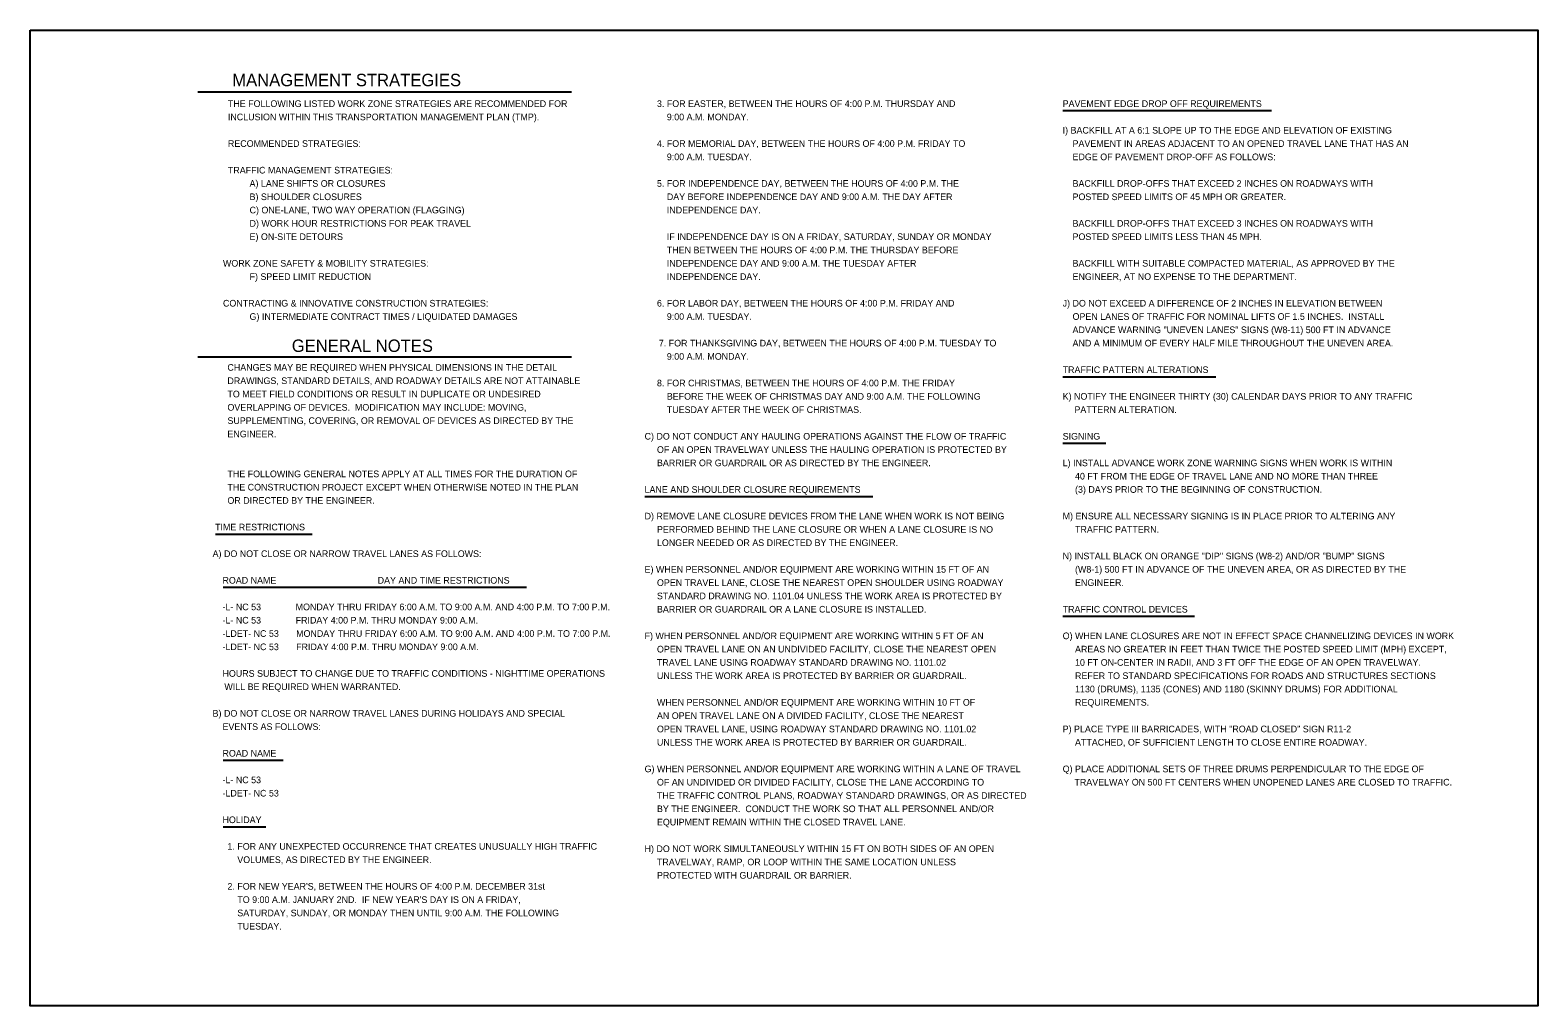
# Model space of a CAD drawing. Extents: x 0 to 3600, y 0 to 1100.
# Drawn here: x 0 to 1700, y 0 to 1100 of the extents above; entities that cross this region are included whole.
import ezdxf

# ---------------------------------------------------------------- set-up
doc = ezdxf.new("R2010")
doc.units = 0
for name, color, linetype in [('DEV BORDER CELL', 7, 'Continuous'), ('Prop Grid Mask', 7, 'Continuous'), ('Sheet Plan CELL', 7, 'Continuous'), ('Sheet_Plan', 7, 'Continuous'), ('Sheet_RDY_XS_Number', 7, 'Continuous')]:
    doc.layers.add(name, color=color, linetype=linetype)

msp = doc.modelspace()

# ---------------------------------------------------------------- linework, layer by layer
at = {"layer": 'DEV BORDER CELL'}
for p, q in [((189, 1030.3), (610.4, 1030.3)), ((189, 731.8), (610.4, 731.8))]:
    msp.add_line(p, q, dxfattribs=at)
at = {"layer": 'Sheet Plan CELL'}
msp.add_lwpolyline([(0, 1100), (1700, 1100), (1700, 0), (0, 0)], close=True, dxfattribs=at)
at = {"layer": 'Sheet_RDY_XS_Number'}
for p, q in [((1164.4, 1009.3), (1399.7, 1009.3)), ((1164.4, 709.3), (1337, 709.3)), ((1164.4, 634.3), (1212.7, 634.3)), ((693, 574.3), (950.3, 574.3)), ((208.8, 531.9), (317.8, 531.9)), ((217.6, 471.9), (559.7, 471.9)), ((1164.4, 439.3), (1313, 439.3)), ((217.6, 276.9), (285.2, 276.9)), ((217.6, 201.9), (265.8, 201.9))]:
    msp.add_line(p, q, dxfattribs=at)

# ---------------------------------------------------------------- texts
at = {"layer": 'Prop Grid Mask'}
for s, p in [('  THE FOLLOWING LISTED WORK ZONE STRATEGIES ARE RECOMMENDED FOR  ', (217.4, 1013.4)), ('            3. FOR EASTER, BETWEEN THE HOURS OF 4:00 P.M. THURSDAY AND', (673.3, 1013.4)), ('       PAVEMENT EDGE DROP OFF REQUIREMENTS', (1144.7, 1013.4)), ('  INCLUSION WITHIN THIS TRANSPORTATION MANAGEMENT PLAN (TMP).  ', (217.4, 998.4)), ('                9:00 A.M. MONDAY.', (673.3, 998.4)), ('       I) BACKFILL AT A 6:1 SLOPE UP TO THE EDGE AND ELEVATION OF EXISTING', (1144.7, 983.4)), ('  RECOMMENDED STRATEGIES:', (217.4, 968.4)), ('            4. FOR MEMORIAL DAY, BETWEEN THE HOURS OF 4:00 P.M. FRIDAY TO', (673.3, 968.4)), ('           PAVEMENT IN AREAS ADJACENT TO AN OPENED TRAVEL LANE THAT HAS AN ', (1144.7, 968.4)), ('                9:00 A.M. TUESDAY.', (673.3, 953.4)), ('           EDGE OF PAVEMENT DROP-OFF AS FOLLOWS:', (1144.7, 953.4)), ('  TRAFFIC MANAGEMENT STRATEGIES:', (217.4, 938.4)), ('A) LANE SHIFTS OR CLOSURES', (247.4, 923.4)), ('            5. FOR INDEPENDENCE DAY, BETWEEN THE HOURS OF 4:00 P.M. THE', (673.3, 923.4)), ('           BACKFILL DROP-OFFS THAT EXCEED 2 INCHES ON ROADWAYS WITH', (1144.7, 923.4)), ('C) ONE-LANE, TWO WAY OPERATION (FLAGGING)', (247.4, 893.4)), ('B) SHOULDER CLOSURES', (247.4, 908.4)), ('                DAY BEFORE INDEPENDENCE DAY AND 9:00 A.M. THE DAY AFTER', (673.3, 908.4)), ('                INDEPENDENCE DAY.', (673.3, 893.4)), ('           POSTED SPEED LIMITS OF 45 MPH OR GREATER.', (1144.7, 908.4)), ('D) WORK HOUR RESTRICTIONS FOR PEAK TRAVEL', (247.4, 878.4)), ('           BACKFILL DROP-OFFS THAT EXCEED 3 INCHES ON ROADWAYS WITH', (1144.7, 878.4)), ('E) ON-SITE DETOURS', (247.4, 863.4)), ('                IF INDEPENDENCE DAY IS ON A FRIDAY, SATURDAY, SUNDAY OR MONDAY  ', (673.3, 863.4)), ('           POSTED SPEED LIMITS LESS THAN 45 MPH.', (1144.7, 863.4)), ('                THEN BETWEEN THE HOURS OF 4:00 P.M. THE THURSDAY BEFORE ', (673.3, 848.4)), ('WORK ZONE SAFETY & MOBILITY STRATEGIES:', (217.4, 833.4)), ('                INDEPENDENCE DAY AND 9:00 A.M. THE TUESDAY AFTER', (673.3, 833.4)), ('           BACKFILL WITH SUITABLE COMPACTED MATERIAL, AS APPROVED BY THE', (1144.7, 833.4)), ('F) SPEED LIMIT REDUCTION', (247.4, 818.4)), ('                INDEPENDENCE DAY.', (673.3, 818.4)), ('           ENGINEER, AT NO EXPENSE TO THE DEPARTMENT.', (1144.7, 818.4)), ('CONTRACTING & INNOVATIVE CONSTRUCTION STRATEGIES:', (217.4, 788.4)), ('            6. FOR LABOR DAY, BETWEEN THE HOURS OF 4:00 P.M. FRIDAY AND', (673.3, 788.4)), ('       J) DO NOT EXCEED A DIFFERENCE OF 2 INCHES IN ELEVATION BETWEEN', (1144.7, 788.4)), ('G) INTERMEDIATE CONTRACT TIMES / LIQUIDATED DAMAGES', (247.4, 773.4)), ('                9:00 A.M. TUESDAY.', (673.3, 773.4)), ('           ADVANCE WARNING "UNEVEN LANES" SIGNS (W8-11) 500 FT IN ADVANCE', (1144.7, 758.4)), ('           OPEN LANES OF TRAFFIC FOR NOMINAL LIFTS OF 1.5 INCHES.  INSTALL ', (1144.7, 773.4)), ('  7. FOR THANKSGIVING DAY, BETWEEN THE HOURS OF 4:00 P.M. TUESDAY TO', (703.3, 743.4)), ('           AND A MINIMUM OF EVERY HALF MILE THROUGHOUT THE UNEVEN AREA.', (1144.7, 743.4)), ('                9:00 A.M. MONDAY.', (673.3, 728.4)), ('            CHANGES MAY BE REQUIRED WHEN PHYSICAL DIMENSIONS IN THE DETAIL ', (189, 716)), ('       TRAFFIC PATTERN ALTERATIONS', (1144.7, 713.4)), ('            DRAWINGS, STANDARD DETAILS, AND ROADWAY DETAILS ARE NOT ATTAINABLE ', (189, 701)), ('            8. FOR CHRISTMAS, BETWEEN THE HOURS OF 4:00 P.M. THE FRIDAY', (673.3, 698.4)), ('            TO MEET FIELD CONDITIONS OR RESULT IN DUPLICATE OR UNDESIRED ', (189, 686)), ('                BEFORE THE WEEK OF CHRISTMAS DAY AND 9:00 A.M. THE FOLLOWING', (673.3, 683.4)), ('       K) NOTIFY THE ENGINEER THIRTY (30) CALENDAR DAYS PRIOR TO ANY TRAFFIC', (1144.7, 683.4)), ('            OVERLAPPING OF DEVICES.  MODIFICATION MAY INCLUDE: MOVING, ', (189, 671)), ('            SUPPLEMENTING, COVERING, OR REMOVAL OF DEVICES AS DIRECTED BY THE ', (189, 656)), ('                TUESDAY AFTER THE WEEK OF CHRISTMAS.', (673.3, 668.4)), (' PATTERN ALTERATION.', (1174.7, 668.4)), ('            ENGINEER.  ', (189, 641)), ('       C) DO NOT CONDUCT ANY HAULING OPERATIONS AGAINST THE FLOW OF TRAFFIC', (673.3, 638.4)), ('       SIGNING', (1144.7, 638.4)), ('            OF AN OPEN TRAVELWAY UNLESS THE HAULING OPERATION IS PROTECTED BY', (673.3, 623.4)), ('            BARRIER OR GUARDRAIL OR AS DIRECTED BY THE ENGINEER.', (673.3, 608.4)), ('       L) INSTALL ADVANCE WORK ZONE WARNING SIGNS WHEN WORK IS WITHIN ', (1144.7, 608.4)), ('            THE FOLLOWING GENERAL NOTES APPLY AT ALL TIMES FOR THE DURATION OF', (189, 596)), ('            40 FT FROM THE EDGE OF TRAVEL LANE AND NO MORE THAN THREE', (1144.7, 593.4)), ('            THE CONSTRUCTION PROJECT EXCEPT WHEN OTHERWISE NOTED IN THE PLAN', (189, 581)), ('       LANE AND SHOULDER CLOSURE REQUIREMENTS', (673.3, 578.4)), ('            (3) DAYS PRIOR TO THE BEGINNING OF CONSTRUCTION.', (1144.7, 578.4)), ('            OR DIRECTED BY THE ENGINEER.', (189, 566)), ('       D) REMOVE LANE CLOSURE DEVICES FROM THE LANE WHEN WORK IS NOT BEING', (673.3, 548.4)), ('       M) ENSURE ALL NECESSARY SIGNING IS IN PLACE PRIOR TO ALTERING ANY', (1144.7, 548.4)), ('       TIME RESTRICTIONS ', (189, 536)), ('            PERFORMED BEHIND THE LANE CLOSURE OR WHEN A LANE CLOSURE IS NO ', (673.3, 533.4)), ('            TRAFFIC PATTERN.', (1144.7, 533.4)), ('      A) DO NOT CLOSE OR NARROW TRAVEL LANES AS FOLLOWS:', (189, 506)), ('            LONGER NEEDED OR AS DIRECTED BY THE ENGINEER.', (673.3, 518.4)), ('       N) INSTALL BLACK ON ORANGE \'\'DIP\'\' SIGNS (W8-2) AND/OR "BUMP" SIGNS  ', (1144.7, 503.4)), ('       E) WHEN PERSONNEL AND/OR EQUIPMENT ARE WORKING WITHIN 15 FT OF AN', (673.3, 488.4)), ('            (W8-1) 500 FT IN ADVANCE OF THE UNEVEN AREA, OR AS DIRECTED BY THE ', (1144.7, 488.4)), ('          ROAD NAME                                         DAY AND TIME RESTRICTIONS', (189, 476)), ('            OPEN TRAVEL LANE, CLOSE THE NEAREST OPEN SHOULDER USING ROADWAY ', (673.3, 473.4)), ('            ENGINEER.  ', (1144.7, 473.4)), ('            STANDARD DRAWING NO. 1101.04 UNLESS THE WORK AREA IS PROTECTED BY ', (673.3, 458.4)), ('          -L- NC 53              MONDAY THRU FRIDAY 6:00 A.M. TO 9:00 A.M. AND 4:00 P.M. TO 7:00 P.M.', (189, 446)), ('            BARRIER OR GUARDRAIL OR A LANE CLOSURE IS INSTALLED.', (673.3, 443.4)), ('       TRAFFIC CONTROL DEVICES', (1144.7, 443.4)), ('          -L- NC 53              FRIDAY 4:00 P.M. THRU MONDAY 9:00 A.M.', (189, 431)), ('          -LDET- NC 53       MONDAY THRU FRIDAY 6:00 A.M. TO 9:00 A.M. AND 4:00 P.M. TO 7:00 P.M.', (189, 416)), ('          -LDET- NC 53       FRIDAY 4:00 P.M. THRU MONDAY 9:00 A.M.', (189, 401)), ('       F) WHEN PERSONNEL AND/OR EQUIPMENT ARE WORKING WITHIN 5 FT OF AN', (673.3, 413.4)), ('       O) WHEN LANE CLOSURES ARE NOT IN EFFECT SPACE CHANNELIZING DEVICES IN WORK', (1144.7, 413.4)), ('            TRAVEL LANE USING ROADWAY STANDARD DRAWING NO. 1101.02', (673.3, 383.4)), ('            OPEN TRAVEL LANE ON AN UNDIVIDED FACILITY, CLOSE THE NEAREST OPEN', (673.3, 398.4)), ('            AREAS NO GREATER IN FEET THAN TWICE THE POSTED SPEED LIMIT (MPH) EXCEPT,', (1144.7, 398.4)), ('            10 FT ON-CENTER IN RADII, AND 3 FT OFF THE EDGE OF AN OPEN TRAVELWAY. ', (1144.7, 383.4)), ('          HOURS SUBJECT TO CHANGE DUE TO TRAFFIC CONDITIONS - NIGHTTIME OPERATIONS', (189, 371)), ('            UNLESS THE WORK AREA IS PROTECTED BY BARRIER OR GUARDRAIL.', (673.3, 368.4)), ('            REFER TO STANDARD SPECIFICATIONS FOR ROADS AND STRUCTURES SECTIONS', (1144.7, 368.4)), ('WILL BE REQUIRED WHEN WARRANTED.', (219, 356)), ('            1130 (DRUMS), 1135 (CONES) AND 1180 (SKINNY DRUMS) FOR ADDITIONAL', (1144.7, 353.4)), ('            WHEN PERSONNEL AND/OR EQUIPMENT ARE WORKING WITHIN 10 FT OF ', (673.3, 338.4)), ('            REQUIREMENTS.', (1144.7, 338.4)), ('      B) DO NOT CLOSE OR NARROW TRAVEL LANES DURING HOLIDAYS AND SPECIAL', (189, 326)), ('            AN OPEN TRAVEL LANE ON A DIVIDED FACILITY, CLOSE THE NEAREST', (673.3, 323.4)), ('          EVENTS AS FOLLOWS:', (189, 311)), ('            OPEN TRAVEL LANE, USING ROADWAY STANDARD DRAWING NO. 1101.02 ', (673.3, 308.4)), ('       P) PLACE TYPE III BARRICADES, WITH "ROAD CLOSED" SIGN R11-2', (1144.7, 308.4)), ('            UNLESS THE WORK AREA IS PROTECTED BY BARRIER OR GUARDRAIL.', (673.3, 293.4)), ('            ATTACHED, OF SUFFICIENT LENGTH TO CLOSE ENTIRE ROADWAY. ', (1144.7, 293.4)), ('          ROAD NAME ', (189, 281)), ('          -L- NC 53', (189, 251)), ('       G) WHEN PERSONNEL AND/OR EQUIPMENT ARE WORKING WITHIN A LANE OF TRAVEL', (673.3, 263.4)), ('            OF AN UNDIVIDED OR DIVIDED FACILITY, CLOSE THE LANE ACCORDING TO', (673.3, 248.4)), ('       Q) PLACE ADDITIONAL SETS OF THREE DRUMS PERPENDICULAR TO THE EDGE OF', (1144.7, 263.4)), (' TRAVELWAY ON 500 FT CENTERS WHEN UNOPENED LANES ARE CLOSED TO TRAFFIC.', (1174.7, 248.4)), ('          -LDET- NC 53', (189, 236)), ('            THE TRAFFIC CONTROL PLANS, ROADWAY STANDARD DRAWINGS, OR AS DIRECTED', (673.3, 233.4)), ('            BY THE ENGINEER.  CONDUCT THE WORK SO THAT ALL PERSONNEL AND/OR ', (673.3, 218.4)), ('          HOLIDAY', (189, 206)), ('            EQUIPMENT REMAIN WITHIN THE CLOSED TRAVEL LANE.', (673.3, 203.4)), ('            1. FOR ANY UNEXPECTED OCCURRENCE THAT CREATES UNUSUALLY HIGH TRAFFIC ', (189, 176)), ('       H) DO NOT WORK SIMULTANEOUSLY WITHIN 15 FT ON BOTH SIDES OF AN OPEN ', (673.3, 173.4)), ('                VOLUMES, AS DIRECTED BY THE ENGINEER.', (189, 161)), ('            TRAVELWAY, RAMP, OR LOOP WITHIN THE SAME LOCATION UNLESS', (673.3, 158.4)), ("            2. FOR NEW YEAR'S, BETWEEN THE HOURS OF 4:00 P.M. DECEMBER 31st", (189, 131)), ('            PROTECTED WITH GUARDRAIL OR BARRIER.', (673.3, 143.4)), ("                TO 9:00 A.M. JANUARY 2ND.  IF NEW YEAR'S DAY IS ON A FRIDAY,", (189, 116)), ('                SATURDAY, SUNDAY, OR MONDAY THEN UNTIL 9:00 A.M. THE FOLLOWING ', (189, 101)), ('                TUESDAY.  ', (189, 86))]:
    msp.add_text(s, height=7.5, dxfattribs=at).set_placement(p)
at = {"layer": 'Sheet_Plan'}
for s, p in [('MANAGEMENT STRATEGIES', (227.9, 1036.8)), ('GENERAL NOTES', (295, 737.2))]:
    msp.add_text(s, height=14, dxfattribs=at).set_placement(p)

doc.saveas('drawing.dxf')
